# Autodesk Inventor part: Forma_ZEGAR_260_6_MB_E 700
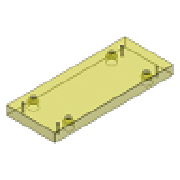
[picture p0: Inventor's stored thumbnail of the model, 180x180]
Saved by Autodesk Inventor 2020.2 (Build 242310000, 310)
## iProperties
IsCustomPart: 1
Manager: www.cadconsulting.pl
Company: Fabian Stasiak CAD Consulting
Created: 2014-02
Part Number: Forma_ZEGAR_260_6_MB_E 700
Material: S 55 C
Description: Ejector Plate
Document SubType Name: Modeling
Designer: F.Stasiak
Standard Revision: 1
Manufacturer: DME
Language: pl-PL
Size Designation: 496x218x22
Categories: <MemberInstance><Categories><Category DisplayName="Forma wtryskowa" InternalName="349578f2-f4d4-4954-8c09-8e99297a61c0" Mnemonic="MOLD"><Category DisplayName="P
Density: 7.85 g/cm^3
Appearance: Clear - Yellow
Catalog Web Link: www.expertbooks.pl
Author: F.Stasiak
Subject: Zbiór ćwiczeń. Autodesk Inventor 2020. Kurs Professional
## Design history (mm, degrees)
sketch "Sketch1"
  geometry: L1 (-109, 248)-(109, 248); L2 (109, 248)-(109, -248); L3 (109, -248)-(-109, -248); L4 (-109, -248)-(-109, 248); 5 further points
  constraints: 8 end point, 2 midpoint, 2 parallel, 1 horizontal, 1 horizontal alignment, 1 perpendicular, 1 vertical alignment
  dimensions: "d92" = 210 vertical distance of point (0, 0) point (-95, 210) (= 0.5 x S2_L); "d93" = 95 horizontal distance of point (0, 0) point (-95, 210) (= 0.5 x S2_W); "d94" = 95 horizontal distance of point (0, 0) point (-95, 233) (= 0.5 x SW_W); "d95" = 233 vertical distance of point (0, 0) point (-95, 233) (= 0.5 x SW_L); "d125" = 218 distance between parallel lines of L2 L4 (= W_); "d126" = 496 distance between parallel lines of L3 L1 (= L)
extrude "Extrusion1" new body sketch "Sketch1" distance "d20" = 22 (= H_); taper "d30" = 0 deg
hole "Hole1" sketch "Sketch1" diameter "d96" = 3.242; stored, may be unused: countersink angle "d100" = 90 deg, drill point angle "d102" = 0 deg; dims "d97" = 6, "d98" = 4, "d99" = 2, "d101" = 22 (= H_)
pattern_linear "Rectangular Pattern1" dims "d112" = 466 (computed from SW_L, Nl), "d115" = 190 (computed from SW_W, Nw)
hole "Hole2" sketch "Sketch1" diameter "d103" = 11 (= S2_d1); stored, may be unused: countersink angle "d107" = 90 deg, drill point angle "d109" = 0 deg; dims "d104" = 6, "d105" = 18 (= S2_d2), "d106" = 12 (= S2_k), "d108" = 22 (= H_)
pattern_linear "Rectangular Pattern2" dims "d118" = 420 (computed from S2_L, Nl), "d121" = 190 (computed from S2_W, Nw)
chamfer "Chamfer1" distance "d122" = 0.5; stored, may be unused: second distance "d123" = 2, angle "d124" = 45 deg
body "Solid1"
other parameters: "L" = 496 [user parameter; used in 1 equation term], "W_" = 218 [user parameter; used in 1 equation term], "H_" = 22 [user parameter; used in 3 equation terms], "S2_d1" = 11 [user parameter; used in 1 equation term], "S2_d2" = 18 [user parameter; used in 1 equation term], "S2_k" = 12 [user parameter; used in 1 equation term], "SW_L" = 466 [user parameter; used in 2 equation terms], "d127" = 54, "d128" = 134, "d129" = 22, "d130" = 0, "d131" = 0, "d132" = -180 deg, "d133" = 24, "d134" = -134, "d135" = 22, "d136" = 0, "d137" = 0, "d138" = 0, "d139" = -24, "d140" = 134, "d141" = 22, "d142" = 0, "d143" = 0, "d144" = -180 deg, "d145" = -54, "d146" = -134, "d147" = 22, "d148" = 0, "d149" = 0, "d150" = 0, "d151" = 24, "d152" = 134, "d153" = 22, "d154" = 0, "d155" = 0, "d156" = -180 deg, "d157" = 54, "d158" = -134, "d159" = 22, "d160" = 0, "d161" = 0, "d162" = 0, "d163" = -54, "d164" = 134, "d165" = 22, "d166" = 0, "d167" = 0, "d168" = -180 deg, "d169" = -24, "d170" = -134, "d171" = 22, "d172" = 0, "d173" = 0, "d174" = 0, "d175" = 54, "d176" = 103.5, "d177" = 22, "d178" = 0, "d179" = 0, "d180" = -180 deg, "d181" = 24, "d182" = -103.5, "d183" = 22, "d184" = 0, "d185" = 0, "d186" = 0, "d187" = -24, "d188" = 103.5, "d189" = 22, "d190" = 0, "d191" = 0, "d192" = -180 deg, "d193" = -54, "d194" = -103.5, "d195" = 22, "d196" = 0, "d197" = 0, "d198" = 0, "d199" = 24, "d200" = 103.5, "d201" = 22, "d202" = 0, "d203" = 0, "d204" = -180 deg, "d205" = 54, "d206" = -103.5, "d207" = 22, "d208" = 0, "d209" = 0, "d210" = 0, "d211" = -54, "d212" = 103.5, "d213" = 22, "d214" = 0, "d215" = 0, "d216" = -180 deg, "d217" = -24, "d218" = -103.5, "d219" = 22, "d220" = 0, "d221" = 0, "d222" = 0, "d223" = 47, "d224" = 71.2, "d225" = 22, "d226" = 0, "d227" = 0, "d228" = -180 deg, "d229" = 31, "d230" = -71.2, "d231" = 22, "d232" = 0, "d233" = 0, "d234" = 0, "d235" = -31, "d236" = 71.2, "d237" = 22, "d238" = 0, "d239" = 0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
